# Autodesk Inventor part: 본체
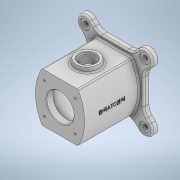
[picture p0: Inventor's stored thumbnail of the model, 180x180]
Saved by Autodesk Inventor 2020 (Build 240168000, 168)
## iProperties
Created: 2022-01
Part Number: 본체
Material: 일반
Document SubType Name: Modeling
Designer: user
Density: 1 g/cm^3
Appearance: 기본값
Author: user
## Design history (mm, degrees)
sketch "스케치1"
  geometry: L1 (-32.942, 45)-(32.942, 45); L2 (32.942, -45)-(-32.942, -45); L3 (-45, 45)-(45, -45); L4 (45, 45)-(-45, -45); A1 r 90 centre (45, 0) between (-32.942, 45) and (-32.942, -45); A2 r 90 centre (-45, 0) between (32.942, -45) and (32.942, 45); 2 further points
  constraints: 8 end point, 6 point on circle, 2 centre point, 2 midpoint, 2 vertical alignment, 1 horizontal, 1 parallel, 1 perpendicular
  dimensions: "d0" = 90 distance of L3.end L4.end; "d1" = 90 distance of L4.start L3.end; "d2" = 90 radius of A1; "d3" = 90 radius of A2; "d4" = 45 deg angle of L3 L1; "d5" = 90 distance between parallel lines of L2 L1; "d6" = 45 distance from line of point (0, 0) L1; "d7" = 0 distance from line of L4.start L1; "d8" = 31.81981 distance from line of A1.centre L3; "d9" = 0 distance from line of L3.start L1
extrude "돌출1" new body sketch "스케치1" distance "d10" = 100; taper "d11" = 0 deg
sketch "스케치2"
  geometry: L1 (53, 53)-(-53, 53); L2 (-53, 53)-(-53, -53); L3 (-53, -53)-(53, -53); L4 (53, -53)-(53, 53); L5 (-54.447, -54.447)-(54.447, 54.447); L6 (-43.841, -65.054)-(65.054, 43.841); L7 (43.841, 65.054)-(-65.054, -43.841); L8 (54.447, -54.447)-(-54.447, 54.447); L9 (65.054, -43.841)-(-43.841, 65.054); L10 (-65.054, 43.841)-(43.841, -65.054); A1 r 15 centre (-54.447, -54.447) between (-65.054, -43.841) and (-43.841, -65.054); A2 r 15 centre (54.447, 54.447) between (65.054, 43.841) and (43.841, 65.054); A3 r 15 centre (54.447, -54.447) between (43.841, -65.054) and (65.054, -43.841); A4 r 15 centre (-54.447, 54.447) between (-43.841, 65.054) and (-65.054, 43.841); 11 further points
  constraints: 24 end point, 8 point on circle, 8 tangent, 4 centre point, 4 midpoint, 4 parallel, 1 horizontal, 1 horizontal alignment, 1 perpendicular, 1 vertical alignment
  dimensions: "d12" = 106 distance of L3.end L2.end; "d13" = 106 distance of L2.end L1.end; "d81" = 45 deg angle of L8 L3; "d82" = 45 deg angle of L5 L3; "d83" = 154 distance of L8.start L8.end; "d84" = 154 distance of L5.end L5.start; "d85" = 30 distance between parallel lines of L6 L7; "d86" = 30 distance between parallel lines of L10 L9
sketch "스케치3"
  geometry: C1 r 25 at (0, 0); 1 further point
  constraints: 1 centre point, 1 coincident
  dimensions: "d19" = 50 diameter of C1
extrude "돌출3" cut sketch "스케치3" distance "d20" = 12; taper "d21" = 0 deg
sketch "스케치4"
  geometry: C1 r 37 at (0, 0); 1 further point
  constraints: 1 centre point, 1 coincident
  dimensions: "d22" = 74 diameter of C1
extrude "돌출4" cut sketch "스케치4" distance "d23" = 86; taper "d24" = 0 deg
sketch "스케치5"
  geometry: C1 r 25 at (0, 0); 1 further point
  constraints: 1 centre point, 1 coincident
  dimensions: "d25" = 50 diameter of C1
extrude "돌출5" cut sketch "스케치5" distance "d26" = 12; taper "d27" = 0 deg
node "작업 평면1"
sketch "스케치6"
  geometry: L1 (53, -10)-(-53, -10) reference; L2 (53, 0)-(-53, 0) reference; C1 r 20 at (0, 50); 6 further points
  constraints: 1 centre point, 1 midpoint, 1 vertical alignment
  dimensions: "d29" = 60 distance from line of L1 C1.centre; "d30" = 40 diameter of C1
extrude "돌출6" join sketch "스케치6" stored distance "d31" = 12; taper "d32" = 15 deg
sketch "스케치7"
  geometry: C1 r 20 at (0, 0) reference; C2 r 15 at (0, 0); 1 further point
  constraints: 1 centre point, 1 coincident
  dimensions: "d33" = 30 diameter of C2
extrude "돌출7" cut sketch "스케치7" distance "d34" = 5; taper "d35" = 0 deg
sketch "스케치8"
  geometry: C1 r 15 at (0, 0) reference; C2 r 12 at (0, 0); 1 further point
  constraints: 1 centre point, 1 coincident
  dimensions: "d36" = 24 diameter of C2
extrude "돌출8" cut sketch "스케치8" stored distance "d37" = 5; taper "d38" = 0 deg
sketch "스케치9" dims "d39" = 80
  geometry: L1 (0, 0)-(-10.788, 0); 5 further points
  constraints: 2 end point, 2 symmetric about line, 1 coincident, 1 horizontal, 3 other
hole "구멍1" sketch "스케치9" at (28.284, 28.284), (-28.284, 28.284), (-28.284, -28.284), (28.284, -28.284) diameter "d41" = 3.242; stored, may be unused: countersink angle "d45" = 90 deg, drill point angle "d47" = 118 deg; dims "d42" = 8, "d43" = 4, "d44" = 2, "d46" = 10
node "작업 평면4"
sketch "스케치10"
  geometry: L1 (0, 0)-(-13.388, 0); C1 r 40 at (0, 0); C2 r 1.621 at (28.284, 28.284) reference; 5 further points
  constraints: 2 coincident, 2 end point, 2 symmetric about line, 1 centre point, 1 horizontal
  dimensions: "d48" = 80 diameter of C1
hole "구멍2" sketch "스케치10" at (28.284, 28.284), (-28.284, 28.284), (-28.284, -28.284), (28.284, -28.284) diameter "d50" = 3.242; stored, may be unused: countersink angle "d54" = 90 deg, drill point angle "d56" = 118 deg; dims "d51" = 8, "d52" = 4, "d53" = 2, "d55" = 10
node "작업 평면3"
sketch "스케치11" dims "d57" = 154
  geometry: L1 (0, 0)-(-75.76, 75.76); L2 (0, 0)-(0, 97.42); L3 (0, 0)-(11.845, 0); C1 r 9 at (-54.447, 54.447); C2 r 9 at (54.447, 54.447); C3 r 9 at (-54.447, -54.447); C4 r 9 at (54.447, -54.447); 1 further point
  constraints: 6 end point, 4 centre point, 3 symmetric about line, 1 coincident, 1 horizontal, 1 point on line, 1 vertical, 6 other
  dimensions: "d58" = 45 deg angle of L1 L2; "d59" = 18 diameter of C1
extrude "돌출9" cut sketch "스케치11" distance "d60" = 2; taper "d61" = 0 deg
node "작업 평면2"
sketch "스케치12"
  geometry: C1 r 4.5 at (-54.447, 54.447); C2 r 4.5 at (-54.447, -54.447); C3 r 4.5 at (54.447, -54.447); C4 r 4.5 at (54.447, 54.447); A1 r 9 centre (-54.447, 54.447) between (-53, 45.564) and (-45.564, 53) reference; A2 r 9 centre (54.447, 54.447) between (45.564, 53) and (53, 45.564) reference; A3 r 9 centre (54.447, -54.447) between (53, -45.564) and (45.564, -53) reference; A4 r 9 centre (-54.447, -54.447) between (-45.564, -53) and (-53, -45.564) reference; 1 further point
  constraints: 4 centre point, 4 coincident
  dimensions: "d62" = 9 diameter of C1; "d63" = 9 diameter of C2; "d64" = 9 diameter of C3; "d65" = 9 diameter of C4
extrude "돌출10" cut sketch "스케치12" extent not by distance; stored distance "d66" = 0; taper "d67" = 0 deg
sketch "스케치13"
  geometry: L1 (25, -10)-(-25, -10) reference; L2 (53, 30)-(53, 70) reference; 2 further points
  constraints: 1 other
  dimensions: "d69" = 60 distance from line of L1 point (0, 50); "d70" = 53 distance from line of L2 point (0, 50)
feature "엠보싱1" sketch "스케치13" dims "d71" = 0.5, "d72" = 0
chamfer "모따기1" distance "d73" = 1; stored, may be unused: second distance "d74" = 2, angle "d75" = 45 deg
fillet "모깎기2" dims "d76" = 3
fillet "모깎기4" dims "d78" = 3
fillet "모깎기5" dims "d79" = 3
extrude "돌출11" join sketch "스케치2" distance "d87" = 10; taper "d88" = 0 deg
sketch "스케치14"
  geometry: C1 r 9 at (-54.447, 54.447); C2 r 9 at (54.447, 54.447); C3 r 9 at (54.447, -54.447); C4 r 9 at (-54.447, -54.447); A1 r 15 centre (-54.447, 54.447) between (-43.841, 65.054) and (-65.054, 43.841) reference; A2 r 15 centre (54.447, 54.447) between (65.054, 43.841) and (43.841, 65.054) reference; A3 r 15 centre (54.447, -54.447) between (43.841, -65.054) and (65.054, -43.841) reference; A4 r 15 centre (-54.447, -54.447) between (-65.054, -43.841) and (-43.841, -65.054) reference; 1 further point
  constraints: 4 centre point, 4 coincident
  dimensions: "d90" = 18 diameter of C1; "d91" = 18 diameter of C2; "d92" = 18 diameter of C3; "d93" = 18 diameter of C4
extrude "돌출12" cut sketch "스케치14" distance "d94" = 2; taper "d95" = 0 deg
sketch "스케치15"
  geometry: C1 r 9 at (-54.447, 54.447) reference; C2 r 9 at (54.447, 54.447) reference; C3 r 9 at (54.447, -54.447) reference; C4 r 9 at (-54.447, -54.447) reference; C5 r 4.5 at (-54.447, 54.447); C6 r 4.5 at (54.447, 54.447); C7 r 4.5 at (54.447, -54.447); C8 r 9 at (-54.447, -54.447) reference; C9 r 4.5 at (-54.447, -54.447); 1 further point
  constraints: 4 centre point, 4 coincident
  dimensions: "d96" = 9 diameter of C5; "d97" = 9 diameter of C6; "d98" = 9 diameter of C7; "d99" = 9 diameter of C9
extrude "돌출13" cut sketch "스케치15" extent not by distance; stored distance "d100" = 0; taper "d101" = 0 deg
sketch "스케치16"
  geometry: C1 r 25 at (0, 0); 1 further point
  constraints: 1 centre point, 1 coincident
  dimensions: "d102" = 50 diameter of C1
extrude "돌출14" cut sketch "스케치16" distance "d103" = 12; taper "d104" = 0 deg
fillet "모깎기7" dims "d105" = 20
sketch "스케치17"
  geometry: L1 (0, 0)-(0, 78.13); L2 (0, 0)-(69.361, 69.361); L3 (0, 0)-(-11.347, 0); C1 r 40 at (0, 0); C2 r 1.621 at (28.284, 28.284) reference; 4 further points
  constraints: 6 end point, 3 symmetric about line, 2 coincident, 1 centre point, 1 horizontal, 1 vertical
  dimensions: "d106" = 80 diameter of C1; "d107" = 45 deg angle of L2 L1
hole "구멍3" sketch "스케치17" at (28.284, 28.284), (-28.284, 28.284), (-28.284, -28.284), (28.284, -28.284) diameter "d108" = 3.242; stored, may be unused: countersink angle "d112" = 90 deg, drill point angle "d114" = 118 deg; dims "d109" = 8, "d110" = 4, "d111" = 2, "d113" = 10
fillet "모깎기8" dims "d115" = 3
chamfer "모따기2" distance "d116" = 1; stored, may be unused: second distance "d117" = 2, angle "d118" = 45 deg
node "솔리드1"
node "투영된 루프1"
node "투영된 루프2"
node "투영된 루프3"
feature "A9D066F2-1C7D-4E18-AEED-F7BC21143FA4" dims "d41" = 3.242, "d42" = 8, "d43" = 4, "d44" = 2, "d45" = 90 deg, "d46" = 10, "d47" = 118 deg
other parameters: "d28" = 53
